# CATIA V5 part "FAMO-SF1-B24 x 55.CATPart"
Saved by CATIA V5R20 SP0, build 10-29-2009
Part number: FAMO-SF1-B24 x 55
Definition: NONE
Nomenclature: FAMO-SF1-B24 x 55
Source: Unknown
Description: FAMO-SF1-B24 x 55
Bounding box of the stored display mesh (mm): x -13 to 42, y -22 to 22, z -22 to 22
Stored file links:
  C:\Users\Utente\Desktop\IO LAVORO\3D X SITO CF\X SITO\FAMO\FAMO-SF1-B24 x 55.CATPart
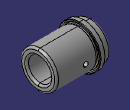
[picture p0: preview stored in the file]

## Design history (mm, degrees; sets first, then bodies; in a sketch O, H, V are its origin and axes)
Body1 "FAMO-SF1-B24 x 55" (main body)
  Solid1: solid without history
